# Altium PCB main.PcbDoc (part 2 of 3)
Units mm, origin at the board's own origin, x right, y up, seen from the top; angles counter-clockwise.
Board outline 326.29 x 232.51 mm, 2 copper layers (TopLayer, BottomLayer); 87 components, 134 nets, 466 pads, 108 vias.
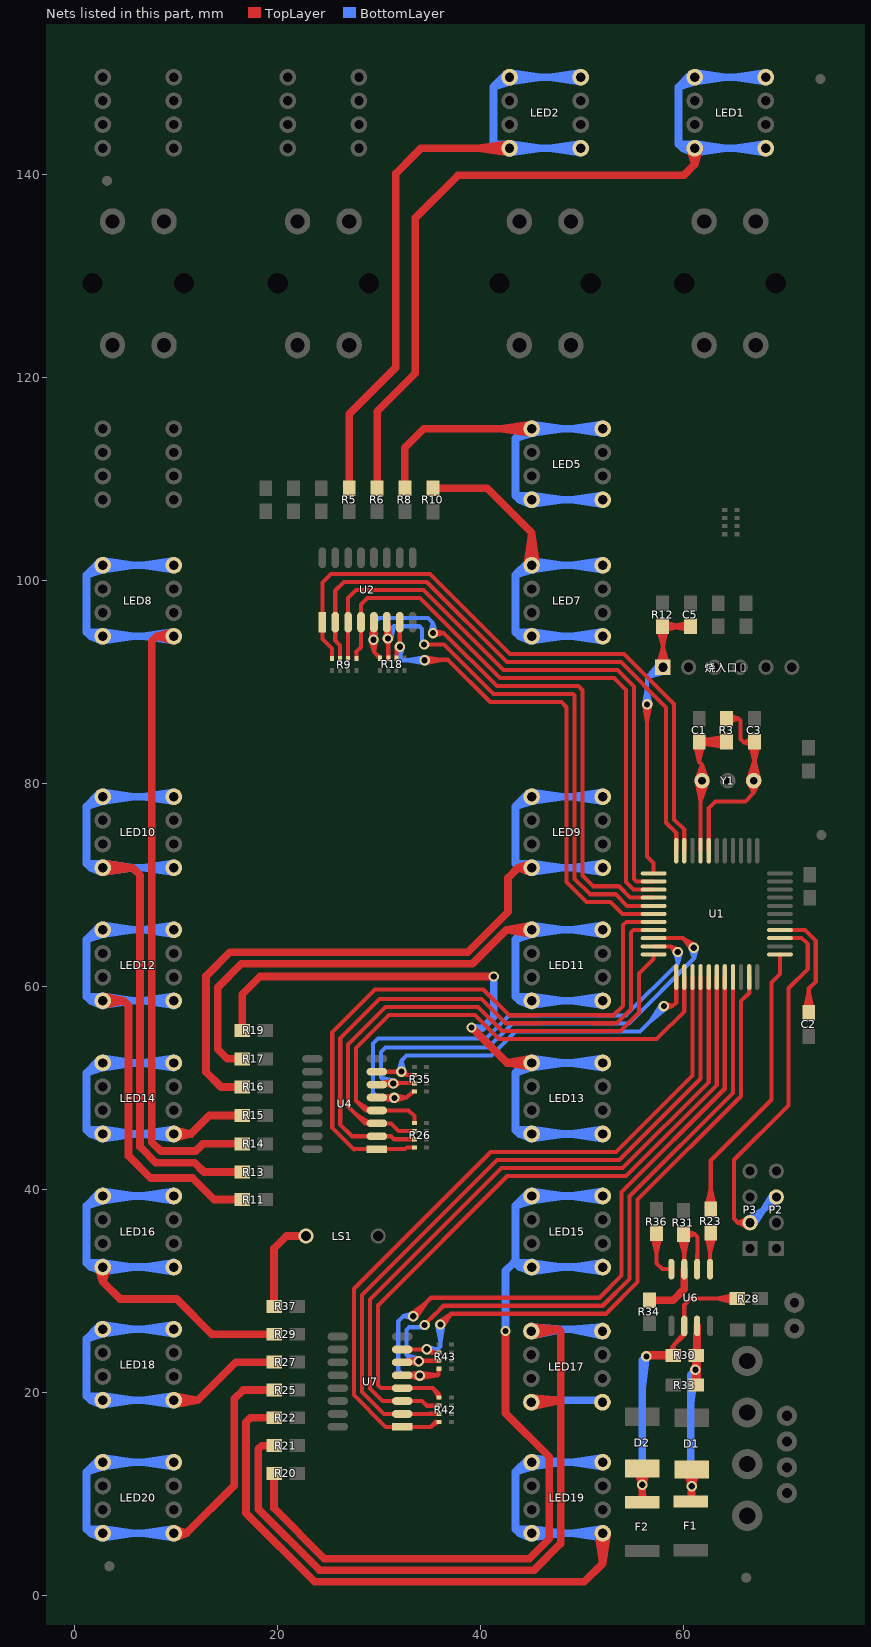
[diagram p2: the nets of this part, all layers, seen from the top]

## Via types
v1: diameter 1.016, hole 0.61, TopLayer to BottomLayer, tented both sides, 108 vias

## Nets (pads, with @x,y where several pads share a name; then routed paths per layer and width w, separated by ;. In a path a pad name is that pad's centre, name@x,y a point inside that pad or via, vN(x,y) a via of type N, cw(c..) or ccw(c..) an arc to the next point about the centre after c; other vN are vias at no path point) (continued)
LEDK4: LED2.K R5.1 | length 129
  TopLayer w0.762: R5.1@27.074,109.072 27.074,116.381 31.648,120.955 31.648,140.056 33.63,142.037 34.143,142.55 LED2.K@42.869,142.55 39.758,142.55 ; R5.1@27.074,109.199 27.074,112.12 ; LED2.K@42.837,142.107 39.758,142.55 ; LED2.K@42.837,142.993 39.758,142.55
  BottomLayer w0.762: LED2.K@42.356,149.669 41.282,148.594 ; LED2.K@42.596,149.901 41.282,148.594 ; LED2.K@42.671,149.55 LED2.K@42.869,149.55 ; LED2.K@42.703,142.138 41.282,142.949 ; LED2.K@42.901,142.107 45.981,142.55 LED2.K@42.901,142.993 ; LED2.K@42.901,149.107 45.981,149.55 LED2.K@42.901,149.993 ; LED2.K@42.918,142.992 41.282,142.949 ; LED2.K@43.051,149.144 41.282,148.594 ; LED2.K@49.671,149.55 LED2.K@42.869,149.55 ; LED2.K@49.837,142.107 46.758,142.55 ; LED2.K@49.837,142.993 46.758,142.55 ; LED2.K@49.837,149.107 46.758,149.55 ; LED2.K@49.837,149.993 46.758,149.55 ; LED2.K@49.869,149.55 46.758,149.55 ; 41.282,142.949 41.681,142.55 ; 41.282,142.949 41.282,148.594 ; 41.282,142.949 LED2.K@42.869,142.55 ; 41.282,148.594 LED2.K@42.869,149.55 ; 41.681,142.55 LED2.K@42.869,142.55 ; 41.681,142.55 42.786,142.113 41.681,142.55 ; 41.681,142.55 42.786,142.987 41.681,142.55 ; 41.681,142.55 LED2.K@42.869,142.55 ; 41.681,142.55 LED2.K@42.869,142.55 ; LED2.K@42.869,142.55 LED2.K@49.869,142.55 46.758,142.55
LEDK5: LED1.K R6.1 | length 138.8
  TopLayer w0.762: R6.1@29.824,109.072 29.824,116.642 33.579,120.396 33.579,135.687 37.795,139.903 58.674,139.903 60.046,139.903 61.099,140.957 ; R6.1@29.824,109.199 29.824,112.12 ; LED1.K@60.659,142.488 61.099,140.957 ; LED1.K@61.539,142.488 61.099,140.957 ; 61.099,140.957 LED1.K@61.099,142.55 61.099,140.957
  BottomLayer w0.762: LED1.K@60.586,149.669 59.512,148.594 ; LED1.K@60.826,149.901 59.512,148.594 ; LED1.K@60.901,149.55 LED1.K@61.099,149.55 ; LED1.K@60.933,142.138 59.512,142.949 ; LED1.K@61.131,142.107 64.211,142.55 LED1.K@61.131,142.993 ; LED1.K@61.131,149.107 64.211,149.55 LED1.K@61.131,149.993 ; LED1.K@61.148,142.992 59.512,142.949 ; LED1.K@61.281,149.144 59.512,148.594 ; LED1.K@67.901,149.55 LED1.K@61.099,149.55 ; LED1.K@68.067,142.107 64.988,142.55 ; LED1.K@68.067,142.993 64.988,142.55 ; LED1.K@68.067,149.107 64.988,149.55 ; LED1.K@68.067,149.993 64.988,149.55 ; LED1.K@68.099,149.55 64.988,149.55 ; 59.512,142.949 59.911,142.55 ; 59.512,142.949 59.512,148.594 ; 59.512,142.949 LED1.K@61.099,142.55 ; 59.512,148.594 LED1.K@61.099,149.55 ; 59.911,142.55 LED1.K@61.099,142.55 ; 59.911,142.55 61.016,142.113 59.911,142.55 ; 59.911,142.55 61.016,142.987 59.911,142.55 ; 59.911,142.55 LED1.K@61.099,142.55 ; 59.911,142.55 LED1.K@61.099,142.55 ; LED1.K@61.099,142.55 LED1.K@68.099,142.55 64.988,142.55
LEDK6: LED5.K R8.1 | length 101.1
  TopLayer w0.762: R8.1@32.549,109.072 32.549,112.051 ; R8.1@32.549,109.199 32.549,112.051 ; LED5.K@45.007,114.487 41.928,114.93 ; LED5.K@45.007,115.373 41.928,114.93 ; 32.549,112.051 32.549,113.067 34.412,114.93 LED5.K@45.039,114.93 41.928,114.93
  BottomLayer w0.762: LED5.K@44.526,115.049 43.452,113.974 ; LED5.K@44.766,115.281 43.452,113.974 ; LED5.K@44.841,114.93 LED5.K@45.039,114.93 ; LED5.K@44.873,107.518 43.452,108.329 ; LED5.K@45.071,107.487 48.151,107.93 LED5.K@45.071,108.373 ; LED5.K@45.071,114.487 48.151,114.93 LED5.K@45.071,115.373 ; LED5.K@45.088,108.372 43.452,108.329 ; LED5.K@45.221,114.524 43.452,113.974 ; LED5.K@51.841,114.93 LED5.K@45.039,114.93 ; LED5.K@52.007,107.487 48.928,107.93 ; LED5.K@52.007,108.373 48.928,107.93 ; LED5.K@52.007,114.487 48.928,114.93 ; LED5.K@52.007,115.373 48.928,114.93 ; LED5.K@52.039,114.93 48.928,114.93 ; 43.452,108.329 43.452,113.974 ; 43.452,108.329 43.851,107.93 ; 43.452,108.329 LED5.K@45.039,107.93 ; 43.452,113.974 LED5.K@45.039,114.93 ; 43.851,107.93 LED5.K@45.039,107.93 ; 43.851,107.93 44.956,107.493 43.851,107.93 ; 43.851,107.93 44.956,108.367 43.851,107.93 ; 43.851,107.93 LED5.K@45.039,107.93 ; 43.851,107.93 LED5.K@45.039,107.93 ; LED5.K@45.039,107.93 LED5.K@52.039,107.93 48.928,107.93
LEDK7: LED7.K R10.1 | length 92.6
  TopLayer w0.762: R10.1@35.307,109.055 40.652,109.055 45.039,104.668 LED7.K@45.039,101.48 ; LED7.K@44.596,101.512 45.039,104.591 LED7.K@45.483,101.512
  BottomLayer w0.762: LED7.K@44.526,101.599 43.452,100.524 ; LED7.K@44.766,101.831 43.452,100.524 ; LED7.K@44.841,101.48 LED7.K@45.039,101.48 ; LED7.K@44.873,94.068 43.452,94.879 ; LED7.K@45.071,94.037 48.151,94.48 LED7.K@45.071,94.923 ; LED7.K@45.071,101.037 48.151,101.48 LED7.K@45.071,101.923 ; LED7.K@45.088,94.922 43.452,94.879 ; LED7.K@45.221,101.074 43.452,100.524 ; LED7.K@51.841,101.48 LED7.K@45.039,101.48 ; LED7.K@52.007,94.037 48.928,94.48 ; LED7.K@52.007,94.923 48.928,94.48 ; LED7.K@52.007,101.037 48.928,101.48 ; LED7.K@52.007,101.923 48.928,101.48 ; LED7.K@52.039,101.48 48.928,101.48 ; 43.452,94.879 43.452,100.524 ; 43.452,94.879 43.851,94.48 ; 43.452,94.879 LED7.K@45.039,94.48 ; 43.452,100.524 LED7.K@45.039,101.48 ; 43.851,94.48 LED7.K@45.039,94.48 ; 43.851,94.48 44.956,94.043 43.851,94.48 ; 43.851,94.48 44.956,94.917 43.851,94.48 ; 43.851,94.48 LED7.K@45.039,94.48 ; 43.851,94.48 LED7.K@45.039,94.48 ; LED7.K@45.039,94.48 LED7.K@52.039,94.48 48.928,94.48
LEDK8: LED12.K R11.1 | length 108.9
  TopLayer w0.762: LED12.K@2.799,58.58 4.869,58.58 ; LED12.K@2.847,58.138 4.869,58.58 ; LED12.K@2.847,59.022 4.869,58.58 ; R11.1@16.417,39.008 13.791,39.008 ; R11.1@16.544,39.008 13.791,39.008 ; 4.869,58.58 5.338,58.111 5.338,43.311 7.524,41.125 11.674,41.125 13.791,39.008
  BottomLayer w0.762: LED12.K@2.286,65.699 1.212,64.624 ; LED12.K@2.526,65.931 1.212,64.624 ; LED12.K@2.601,65.58 LED12.K@2.799,65.58 ; LED12.K@2.633,58.168 1.212,58.979 ; LED12.K@2.831,58.137 5.911,58.58 LED12.K@2.831,59.023 ; LED12.K@2.831,65.137 5.911,65.58 LED12.K@2.831,66.023 ; LED12.K@2.848,59.022 1.212,58.979 ; LED12.K@2.981,65.174 1.212,64.624 ; LED12.K@9.601,65.58 LED12.K@2.799,65.58 ; LED12.K@9.767,58.137 6.688,58.58 ; LED12.K@9.767,59.023 6.688,58.58 ; LED12.K@9.767,65.137 6.688,65.58 ; LED12.K@9.767,66.023 6.688,65.58 ; LED12.K@9.799,65.58 6.688,65.58 ; 1.212,58.979 1.212,64.624 ; 1.212,58.979 1.611,58.58 ; 1.212,58.979 LED12.K@2.799,58.58 ; 1.212,64.624 LED12.K@2.799,65.58 ; 1.611,58.58 LED12.K@2.799,58.58 ; 1.611,58.58 2.716,58.143 1.611,58.58 ; 1.611,58.58 2.716,59.017 1.611,58.58 ; 1.611,58.58 LED12.K@2.799,58.58 ; 1.611,58.58 LED12.K@2.799,58.58 ; LED12.K@2.799,58.58 LED12.K@9.799,58.58 6.688,58.58
LEDK9: LED10.K R13.1 | length 122.2
  TopLayer w0.762: LED10.K@2.799,71.69 5.729,71.69 ; LED10.K@2.833,71.247 5.729,71.69 ; LED10.K@2.833,72.133 5.729,71.69 ; 13.479,41.725 R13.1@16.4,41.725 ; R13.1@16.527,41.725 12.774,41.725 11.849,42.65 8.033,42.65 6.481,44.202 6.481,70.938 5.729,71.69
  BottomLayer w0.762: LED10.K@2.286,78.809 1.212,77.734 ; LED10.K@2.526,79.041 1.212,77.734 ; LED10.K@2.601,78.69 LED10.K@2.799,78.69 ; LED10.K@2.633,71.278 1.212,72.089 ; LED10.K@2.831,71.247 5.911,71.69 LED10.K@2.831,72.133 ; LED10.K@2.831,78.247 5.911,78.69 LED10.K@2.831,79.133 ; LED10.K@2.848,72.132 1.212,72.089 ; LED10.K@2.981,78.284 1.212,77.734 ; LED10.K@9.601,78.69 LED10.K@2.799,78.69 ; LED10.K@9.767,71.247 6.688,71.69 ; LED10.K@9.767,72.133 6.688,71.69 ; LED10.K@9.767,78.247 6.688,78.69 ; LED10.K@9.767,79.133 6.688,78.69 ; LED10.K@9.799,78.69 6.688,78.69 ; 1.212,72.089 1.212,77.734 ; 1.212,72.089 1.611,71.69 ; 1.212,72.089 LED10.K@2.799,71.69 ; 1.212,77.734 LED10.K@2.799,78.69 ; 1.611,71.69 LED10.K@2.799,71.69 ; 1.611,71.69 2.716,71.253 1.611,71.69 ; 1.611,71.69 2.716,72.127 1.611,71.69 ; 1.611,71.69 LED10.K@2.799,71.69 ; 1.611,71.69 LED10.K@2.799,71.69 ; LED10.K@2.799,71.69 LED10.K@9.799,71.69 6.688,71.69
LEDK10: LED8.K R14.1 | length 140.8
  TopLayer w0.762: LED8.K@9.74,94.039 8.12,94.48 ; LED8.K@9.74,94.921 8.12,94.48 ; 13.479,44.5 R14.1@16.4,44.5 ; R14.1@16.527,44.5 12.674,44.5 11.967,43.793 8.506,43.793 7.624,44.675 7.624,93.984 8.12,94.48 ; 8.12,94.48 LED8.K@9.799,94.48 8.12,94.48
  BottomLayer w0.762: LED8.K@2.286,101.599 1.212,100.524 ; LED8.K@2.526,101.831 1.212,100.524 ; LED8.K@2.601,101.48 LED8.K@2.799,101.48 ; LED8.K@2.633,94.068 1.212,94.879 ; LED8.K@2.831,94.037 5.911,94.48 LED8.K@2.831,94.923 ; LED8.K@2.831,101.037 5.911,101.48 LED8.K@2.831,101.923 ; LED8.K@2.848,94.922 1.212,94.879 ; LED8.K@2.981,101.074 1.212,100.524 ; LED8.K@9.601,101.48 LED8.K@2.799,101.48 ; LED8.K@9.767,94.037 6.688,94.48 ; LED8.K@9.767,94.923 6.688,94.48 ; LED8.K@9.767,101.037 6.688,101.48 ; LED8.K@9.767,101.923 6.688,101.48 ; LED8.K@9.799,101.48 6.688,101.48 ; 1.212,94.879 1.212,100.524 ; 1.212,94.879 1.611,94.48 ; 1.212,94.879 LED8.K@2.799,94.48 ; 1.212,100.524 LED8.K@2.799,101.48 ; 1.611,94.48 LED8.K@2.799,94.48 ; 1.611,94.48 2.716,94.043 1.611,94.48 ; 1.611,94.48 2.716,94.917 1.611,94.48 ; 1.611,94.48 LED8.K@2.799,94.48 ; 1.611,94.48 LED8.K@2.799,94.48 ; LED8.K@2.799,94.48 LED8.K@9.799,94.48 6.688,94.48
LEDK11: LED14.K R15.1 | length 85.4
  TopLayer w0.762: LED14.K@9.799,45.47 11.485,45.47 ; LED14.K@9.858,45.029 11.485,45.47 ; LED14.K@9.858,45.911 11.485,45.47 ; 13.479,47.3 R15.1@16.4,47.3 ; R15.1@16.527,47.3 13.315,47.3 11.485,45.47
  BottomLayer w0.762: LED14.K@2.286,52.589 1.212,51.514 ; LED14.K@2.526,52.821 1.212,51.514 ; LED14.K@2.601,52.47 LED14.K@2.799,52.47 ; LED14.K@2.633,45.058 1.212,45.869 ; LED14.K@2.831,45.027 5.911,45.47 LED14.K@2.831,45.913 ; LED14.K@2.831,52.027 5.911,52.47 LED14.K@2.831,52.913 ; LED14.K@2.848,45.912 1.212,45.869 ; LED14.K@2.981,52.064 1.212,51.514 ; LED14.K@9.601,52.47 LED14.K@2.799,52.47 ; LED14.K@9.767,45.027 6.688,45.47 ; LED14.K@9.767,45.913 6.688,45.47 ; LED14.K@9.767,52.027 6.688,52.47 ; LED14.K@9.767,52.913 6.688,52.47 ; LED14.K@9.799,52.47 6.688,52.47 ; 1.212,45.869 1.212,51.514 ; 1.212,45.869 1.611,45.47 ; 1.212,45.869 LED14.K@2.799,45.47 ; 1.212,51.514 LED14.K@2.799,52.47 ; 1.611,45.47 LED14.K@2.799,45.47 ; 1.611,45.47 2.716,45.033 1.611,45.47 ; 1.611,45.47 2.716,45.907 1.611,45.47 ; 1.611,45.47 LED14.K@2.799,45.47 ; 1.611,45.47 LED14.K@2.799,45.47 ; LED14.K@2.799,45.47 LED14.K@9.799,45.47 6.688,45.47
LEDK12: LED9.K R16.1 | length 129.7
  TopLayer w0.762: R16.1@16.4,50.1 14.449,50.1 ; R16.1@16.527,50.1 14.449,50.1 ; LED9.K@44.965,71.252 43.699,71.69 ; LED9.K@44.965,72.128 43.699,71.69 ; 14.449,50.1 12.981,51.568 12.981,61.032 15.317,63.368 38.739,63.368 42.723,67.352 42.723,70.714 43.699,71.69 ; 43.699,71.69 LED9.K@45.039,71.69 43.699,71.69
  BottomLayer w0.762: LED9.K@44.526,78.809 43.452,77.734 ; LED9.K@44.766,79.041 43.452,77.734 ; LED9.K@44.841,78.69 LED9.K@45.039,78.69 ; LED9.K@44.873,71.278 43.452,72.089 ; LED9.K@45.071,71.247 48.151,71.69 LED9.K@45.071,72.133 ; LED9.K@45.071,78.247 48.151,78.69 LED9.K@45.071,79.133 ; LED9.K@45.088,72.132 43.452,72.089 ; LED9.K@45.221,78.284 43.452,77.734 ; LED9.K@51.841,78.69 LED9.K@45.039,78.69 ; LED9.K@52.007,71.247 48.928,71.69 ; LED9.K@52.007,72.133 48.928,71.69 ; LED9.K@52.007,78.247 48.928,78.69 ; LED9.K@52.007,79.133 48.928,78.69 ; LED9.K@52.039,78.69 48.928,78.69 ; 43.452,72.089 43.452,77.734 ; 43.452,72.089 43.851,71.69 ; 43.452,72.089 LED9.K@45.039,71.69 ; 43.452,77.734 LED9.K@45.039,78.69 ; 43.851,71.69 LED9.K@45.039,71.69 ; 43.851,71.69 44.956,71.253 43.851,71.69 ; 43.851,71.69 44.956,72.127 43.851,71.69 ; 43.851,71.69 LED9.K@45.039,71.69 ; 43.851,71.69 LED9.K@45.039,71.69 ; LED9.K@45.039,71.69 LED9.K@52.039,71.69 48.928,71.69
LEDK13: LED11.K R17.1 | length 122.5
  TopLayer w0.762: R17.1@16.4,52.875 15.074,52.875 ; R17.1@16.527,52.875 15.074,52.875 ; LED11.K@44.999,65.137 42.568,65.58 ; LED11.K@44.999,66.023 42.568,65.58 ; 15.074,52.875 14.124,53.825 14.124,59.9 16.449,62.225 39.213,62.225 42.568,65.58 ; 42.568,65.58 LED11.K@45.039,65.58 42.568,65.58
  BottomLayer w0.762: LED11.K@44.526,65.699 43.452,64.624 ; LED11.K@44.766,65.931 43.452,64.624 ; LED11.K@44.841,65.58 LED11.K@45.039,65.58 ; LED11.K@44.873,58.168 43.452,58.979 ; LED11.K@45.071,58.137 48.151,58.58 LED11.K@45.071,59.023 ; LED11.K@45.071,65.137 48.151,65.58 LED11.K@45.071,66.023 ; LED11.K@45.088,59.022 43.452,58.979 ; LED11.K@45.221,65.174 43.452,64.624 ; LED11.K@51.841,65.58 LED11.K@45.039,65.58 ; LED11.K@52.007,58.137 48.928,58.58 ; LED11.K@52.007,59.023 48.928,58.58 ; LED11.K@52.007,65.137 48.928,65.58 ; LED11.K@52.007,66.023 48.928,65.58 ; LED11.K@52.039,65.58 48.928,65.58 ; 43.452,58.979 43.452,64.624 ; 43.452,58.979 43.851,58.58 ; 43.452,58.979 LED11.K@45.039,58.58 ; 43.452,64.624 LED11.K@45.039,65.58 ; 43.851,58.58 LED11.K@45.039,58.58 ; 43.851,58.58 44.956,58.143 43.851,58.58 ; 43.851,58.58 44.956,59.017 43.851,58.58 ; 43.851,58.58 LED11.K@45.039,58.58 ; 43.851,58.58 LED11.K@45.039,58.58 ; LED11.K@45.039,58.58 LED11.K@52.039,58.58 48.928,58.58
LEDK14: LED13.K R19.1 | length 128.6
  TopLayer w0.762: R19.1@16.527,55.675 16.527,59.225 18.277,60.975 v1(41.3,60.975) 38.506,60.975 ; v1(39.114,55.967) 42.611,52.47 ; LED13.K@44.998,52.027 42.611,52.47 ; LED13.K@44.998,52.913 42.611,52.47 ; 42.611,52.47 LED13.K@45.039,52.47 42.611,52.47
  BottomLayer w0.762: 41.3,58.181 v1(41.3,60.975) 41.3,57.007 40.173,55.88 ; LED13.K@44.526,52.589 43.452,51.514 ; LED13.K@44.766,52.821 43.452,51.514 ; LED13.K@44.841,52.47 LED13.K@45.039,52.47 ; LED13.K@44.873,45.058 43.452,45.869 ; LED13.K@45.071,45.027 48.151,45.47 LED13.K@45.071,45.913 ; LED13.K@45.071,52.027 48.151,52.47 LED13.K@45.071,52.913 ; LED13.K@45.088,45.912 43.452,45.869 ; LED13.K@45.221,52.064 43.452,51.514 ; LED13.K@51.841,52.47 LED13.K@45.039,52.47 ; LED13.K@52.007,45.027 48.928,45.47 ; LED13.K@52.007,45.913 48.928,45.47 ; LED13.K@52.007,52.027 48.928,52.47 ; LED13.K@52.007,52.913 48.928,52.47 ; LED13.K@52.039,52.47 48.928,52.47 ; 40.173,55.88 39.201,55.88 v1(39.114,55.967) 40.173,55.88 ; 43.452,45.869 43.452,51.514 ; 43.452,45.869 43.851,45.47 ; 43.452,45.869 LED13.K@45.039,45.47 ; 43.452,51.514 LED13.K@45.039,52.47 ; 43.851,45.47 LED13.K@45.039,45.47 ; 43.851,45.47 44.956,45.033 43.851,45.47 ; 43.851,45.47 44.956,45.907 43.851,45.47 ; 43.851,45.47 LED13.K@45.039,45.47 ; 43.851,45.47 LED13.K@45.039,45.47 ; LED13.K@45.039,45.47 LED13.K@52.039,45.47 48.928,45.47
LEDK15: LED15.K R20.1 | length 140.2
  TopLayer w0.762: 19.677,9.129 R20.1@19.677,12.05 19.677,8.6 24.627,3.65 44.794,3.65 46.769,5.625 46.769,13.683 42.469,17.983 v1(42.469,26.06) 42.469,23.266
  BottomLayer w0.762: v1(42.469,26.06) 42.469,32.004 43.224,32.759 43.452,32.759 ; LED15.K@44.526,39.479 43.452,38.404 ; LED15.K@44.766,39.711 43.452,38.404 ; LED15.K@44.841,39.36 LED15.K@45.039,39.36 ; LED15.K@44.873,31.948 43.452,32.759 ; LED15.K@45.071,31.917 48.151,32.36 LED15.K@45.071,32.803 ; LED15.K@45.071,38.917 48.151,39.36 LED15.K@45.071,39.803 ; LED15.K@45.088,32.802 43.452,32.759 ; LED15.K@45.221,38.954 43.452,38.404 ; LED15.K@51.841,39.36 LED15.K@45.039,39.36 ; LED15.K@52.007,31.917 48.928,32.36 ; LED15.K@52.007,32.803 48.928,32.36 ; LED15.K@52.007,38.917 48.928,39.36 ; LED15.K@52.007,39.803 48.928,39.36 ; LED15.K@52.039,39.36 48.928,39.36 ; 43.452,32.759 43.452,38.404 ; 43.452,32.759 43.851,32.36 ; 43.452,32.759 LED15.K@45.039,32.36 ; 43.452,38.404 LED15.K@45.039,39.36 ; 43.851,32.36 LED15.K@45.039,32.36 ; 43.851,32.36 44.956,31.923 43.851,32.36 ; 43.851,32.36 44.956,32.797 43.851,32.36 ; 43.851,32.36 LED15.K@45.039,32.36 ; 43.851,32.36 LED15.K@45.039,32.36 ; LED15.K@45.039,32.36 LED15.K@52.039,32.36 48.928,32.36
LEDK16: LED17.K R21.1 | length 118.5
  TopLayer w0.762: R21.1@19.55,14.775 18.449,14.775 ; R21.1@19.677,14.775 18.449,14.775 ; LED17.K@45.014,19.055 47.912,19.25 ; LED17.K@45.014,26.055 47.715,26.25 ; LED17.K@45.018,19.5 47.912,19.25 ; LED17.K@45.019,26.5 47.715,26.25 ; LED17.K@45.039,19.25 47.912,19.25 ; LED17.K@45.039,26.25 47.715,26.25 ; LED17.K@45.078,18.615 47.912,19.25 ; LED17.K@45.082,25.616 47.715,26.25 ; 18.449,14.775 18.124,14.45 18.124,8.536 24.154,2.507 45.268,2.507 47.912,5.152 47.912,26.053 47.715,26.25
  BottomLayer w0.762: LED17.K@44.841,26.25 45.039,26.25 LED17.K@51.841,26.25 ; LED17.K@45.014,26.055 48.144,26.25 ; LED17.K@45.018,26.5 48.144,26.25 ; LED17.K@45.039,19.25 LED17.K@52.039,19.25 ; LED17.K@45.073,25.615 48.144,26.25 ; LED17.K@51.955,25.615 48.88,26.25 ; LED17.K@52.01,26.5 48.88,26.25 ; LED17.K@52.014,26.055 48.88,26.25
LEDK17: LED19.K R22.1 | length 133.3
  TopLayer w0.762: R22.1@19.55,17.525 17.349,17.525 ; R22.1@19.677,17.525 17.349,17.525 ; LED19.K@51.596,6.107 52.039,3.17 ; LED19.K@52.039,6.14 52.039,3.17 ; LED19.K@52.482,6.107 52.039,3.17 ; 17.349,17.525 16.899,17.075 16.899,8.145 23.68,1.364 50.234,1.364 52.039,3.17
  BottomLayer w0.762: LED19.K@44.526,13.259 43.452,12.184 ; LED19.K@44.766,13.491 43.452,12.184 ; LED19.K@44.841,13.14 LED19.K@45.039,13.14 ; LED19.K@44.873,5.728 43.452,6.539 ; LED19.K@45.071,5.697 48.151,6.14 LED19.K@45.071,6.583 ; LED19.K@45.071,12.697 48.151,13.14 LED19.K@45.071,13.583 ; LED19.K@45.088,6.582 43.452,6.539 ; LED19.K@45.221,12.734 43.452,12.184 ; LED19.K@51.841,13.14 LED19.K@45.039,13.14 ; LED19.K@52.007,5.697 48.928,6.14 ; LED19.K@52.007,6.583 48.928,6.14 ; LED19.K@52.007,12.697 48.928,13.14 ; LED19.K@52.007,13.583 48.928,13.14 ; LED19.K@52.039,13.14 48.928,13.14 ; 43.452,6.539 43.452,12.184 ; 43.452,6.539 43.851,6.14 ; 43.452,6.539 LED19.K@45.039,6.14 ; 43.452,12.184 LED19.K@45.039,13.14 ; 43.851,6.14 LED19.K@45.039,6.14 ; 43.851,6.14 44.956,5.703 43.851,6.14 ; 43.851,6.14 44.956,6.577 43.851,6.14 ; 43.851,6.14 LED19.K@45.039,6.14 ; 43.851,6.14 LED19.K@45.039,6.14 ; LED19.K@45.039,6.14 LED19.K@52.039,6.14 48.928,6.14
LEDK18: LED20.K R25.1 | length 97.8
  TopLayer w0.762: LED20.K@9.799,6.14 11.04,6.14 ; LED20.K@9.879,5.703 11.04,6.14 ; LED20.K@9.879,6.577 11.04,6.14 ; 16.629,20.25 R25.1@19.55,20.25 ; R25.1@19.677,20.25 16.624,20.25 15.756,19.382 15.756,10.856 11.04,6.14
  BottomLayer w0.762: LED20.K@2.286,13.259 1.212,12.184 ; LED20.K@2.526,13.491 1.212,12.184 ; LED20.K@2.601,13.14 LED20.K@2.799,13.14 ; LED20.K@2.633,5.728 1.212,6.539 ; LED20.K@2.831,5.697 5.911,6.14 LED20.K@2.831,6.583 ; LED20.K@2.831,12.697 5.911,13.14 LED20.K@2.831,13.583 ; LED20.K@2.848,6.582 1.212,6.539 ; LED20.K@2.981,12.734 1.212,12.184 ; LED20.K@9.601,13.14 LED20.K@2.799,13.14 ; LED20.K@9.767,5.697 6.688,6.14 ; LED20.K@9.767,6.583 6.688,6.14 ; LED20.K@9.767,12.697 6.688,13.14 ; LED20.K@9.767,13.583 6.688,13.14 ; LED20.K@9.799,13.14 6.688,13.14 ; 1.212,6.539 1.611,6.14 ; 1.212,6.539 1.212,12.184 ; 1.212,6.539 LED20.K@2.799,6.14 ; 1.212,12.184 LED20.K@2.799,13.14 ; 1.611,6.14 LED20.K@2.799,6.14 ; 1.611,6.14 2.716,5.703 1.611,6.14 ; 1.611,6.14 2.716,6.577 1.611,6.14 ; 1.611,6.14 LED20.K@2.799,6.14 ; 1.611,6.14 LED20.K@2.799,6.14 ; LED20.K@2.799,6.14 LED20.K@9.799,6.14 6.688,6.14
LEDK19: LED18.K R27.1 | length 90.7
  TopLayer w0.762: LED18.K@9.799,19.25 12.149,19.25 ; LED18.K@9.841,18.807 12.149,19.25 ; LED18.K@9.841,19.692 12.149,19.25 ; 16.629,23 R27.1@19.55,23 ; R27.1@19.677,23 15.899,23 12.149,19.25
  BottomLayer w0.762: LED18.K@2.286,26.369 1.212,25.294 ; LED18.K@2.526,26.601 1.212,25.294 ; LED18.K@2.601,26.25 LED18.K@2.799,26.25 ; LED18.K@2.633,18.838 1.212,19.649 ; LED18.K@2.831,18.807 5.911,19.25 LED18.K@2.831,19.693 ; LED18.K@2.831,25.807 5.911,26.25 LED18.K@2.831,26.693 ; LED18.K@2.848,19.692 1.212,19.649 ; LED18.K@2.981,25.844 1.212,25.294 ; LED18.K@9.601,26.25 LED18.K@2.799,26.25 ; LED18.K@9.767,18.807 6.688,19.25 ; LED18.K@9.767,19.693 6.688,19.25 ; LED18.K@9.767,25.807 6.688,26.25 ; LED18.K@9.767,26.693 6.688,26.25 ; LED18.K@9.799,26.25 6.688,26.25 ; 1.212,19.649 1.212,25.294 ; 1.212,19.649 1.611,19.25 ; 1.212,19.649 LED18.K@2.799,19.25 ; 1.212,25.294 LED18.K@2.799,26.25 ; 1.611,19.25 LED18.K@2.799,19.25 ; 1.611,19.25 2.716,18.813 1.611,19.25 ; 1.611,19.25 2.716,19.687 1.611,19.25 ; 1.611,19.25 LED18.K@2.799,19.25 ; 1.611,19.25 LED18.K@2.799,19.25 ; LED18.K@2.799,19.25 LED18.K@9.799,19.25 6.688,19.25
LEDK20: LED16.K R29.1 | length 99.3
  TopLayer w0.762: LED16.K@2.36,32.291 2.799,30.932 ; LED16.K@3.238,32.291 2.799,30.932 ; 16.629,25.75 R29.1@19.55,25.75 ; R29.1@19.677,25.75 13.549,25.75 10.074,29.225 4.506,29.225 2.799,30.932 ; 2.799,30.932 LED16.K@2.799,32.36 2.799,30.932
  BottomLayer w0.762: LED16.K@2.286,39.479 1.212,38.404 ; LED16.K@2.526,39.711 1.212,38.404 ; LED16.K@2.601,39.36 LED16.K@2.799,39.36 ; LED16.K@2.633,31.948 1.212,32.759 ; LED16.K@2.831,31.917 5.911,32.36 LED16.K@2.831,32.803 ; LED16.K@2.831,38.917 5.911,39.36 LED16.K@2.831,39.803 ; LED16.K@2.848,32.802 1.212,32.759 ; LED16.K@2.981,38.954 1.212,38.404 ; LED16.K@9.601,39.36 LED16.K@2.799,39.36 ; LED16.K@9.767,31.917 6.688,32.36 ; LED16.K@9.767,32.803 6.688,32.36 ; LED16.K@9.767,38.917 6.688,39.36 ; LED16.K@9.767,39.803 6.688,39.36 ; LED16.K@9.799,39.36 6.688,39.36 ; 1.212,32.759 1.212,38.404 ; 1.212,32.759 1.611,32.36 ; 1.212,32.759 LED16.K@2.799,32.36 ; 1.212,38.404 LED16.K@2.799,39.36 ; 1.611,32.36 LED16.K@2.799,32.36 ; 1.611,32.36 2.716,31.923 1.611,32.36 ; 1.611,32.36 2.716,32.797 1.611,32.36 ; 1.611,32.36 LED16.K@2.799,32.36 ; 1.611,32.36 LED16.K@2.799,32.36 ; LED16.K@2.799,32.36 LED16.K@9.799,32.36 6.688,32.36
LOUT1: R9.8 U1.10 U2.1 | length 67.6
  TopLayer w0.406: U2.1@24.429,95.24 24.429,94.22 ; U2.1@24.429,96.51 24.429,98.11 ; R9.8@25.374,92.3 25.374,93.275 ; R9.8@25.374,92.35 25.374,93.275 ; U1.10@60.074,73.373 60.074,75.45 ; U1.10@60.074,74.44 60.074,75.45 ; 24.429,94.22 25.374,93.275 ; 24.429,94.22 U2.1@24.429,95.875 24.429,99.769 25.273,100.612 35.037,100.612 42.924,92.725 54.149,92.725 59.074,87.8 59.074,76.45 60.074,75.45
LOUT2: R9.7 U1.11 U2.2 | length 64.1
  TopLayer w0.406: U2.2@25.699,95.24 25.699,94.064 ; U2.2@25.699,96.51 25.699,98.11 ; R9.7@26.174,92.3 26.174,93.589 ; R9.7@26.174,92.35 26.174,93.589 ; U1.11@59.286,73.373 59.286,75.124 ; U1.11@59.286,74.44 59.286,75.124 ; 25.699,94.064 U2.2@25.699,95.875 25.699,98.975 26.549,99.825 34.708,99.825 42.596,91.938 53.823,91.938 58.287,87.474 58.287,76.124 59.286,75.124 ; 25.699,94.064 26.174,93.589
LOUT3: R9.6 U1.13 U2.3 | length 63.1
  TopLayer w0.406: 26.969,93.64 U2.3@26.969,95.24 ; U2.3@26.969,96.51 26.969,98.11 ; R9.6@26.974,92.3 26.969,92.305 U2.3@26.969,95.875 26.969,98.245 27.761,99.037 34.382,99.037 42.269,91.15 53.497,91.15 55.124,89.523 55.124,70.6 55.374,70.35 ; U1.13@55.984,70.35 55.374,70.35 ; U1.13@57.051,70.35 55.374,70.35
LOUT4: R9.5 U1.14 U2.4 | length 61.7
  TopLayer w0.406: R9.5@27.774,92.3 27.774,92.907 ; R9.5@27.774,92.35 27.774,92.907 ; 28.239,93.64 U2.4@28.239,95.24 ; U2.4@28.239,96.51 28.239,97.603 ; U1.14@55.984,69.538 55.073,69.538 ; U1.14@57.051,69.538 55.073,69.538 ; 27.774,92.907 27.757,92.925 28.239,93.408 U2.4@28.239,95.875 28.239,97.603 ; 28.239,97.603 28.886,98.25 34.056,98.25 41.943,90.363 53.171,90.363 54.337,89.197 54.337,70.274 55.073,69.538
LOUT5: R18.8 U1.15 U2.5 | length 79.4
  TopLayer w0.406: v1@29.171,94.183 U2.5@29.509,95.875 ; v1@29.173,94.103 29.509,92.94 ; v1@29.174,94.202 U2.5@29.509,95.24 ; v1@29.777,94.183 U2.5@29.509,95.24 ; v1@29.778,94.12 29.509,92.94 ; v1@29.778,94.171 U2.5@29.509,95.875 ; R18.8@30.124,92.325 29.509,92.94 ; R18.8@30.124,92.375 29.509,92.94 ; v1@35.362,95.102 36.371,94.822 ; v1@35.375,94.499 36.371,94.822 ; U1.15@55.984,68.75 54.747,68.75 ; U1.15@57.051,68.75 54.747,68.75 ; v1(29.474,94.15) v1@29.509,94.15 ; v1(29.474,94.15) U2.5@29.509,95.24 ; v1(29.474,94.15) 29.509,92.94 ; v1(29.474,94.15) U2.5@29.509,95.875 ; 29.509,92.94 v1@29.509,94.15 ; v1@29.509,94.15 U2.5@29.509,95.875 ; v1@29.509,94.15 U2.5@29.509,95.24 ; 36.371,94.822 35.346,94.822 v1(35.324,94.8) 36.371,94.822 ; 36.371,94.822 41.617,89.575 49.649,89.575 50.049,89.175 50.049,70.925 51.099,69.875 53.622,69.875 54.747,68.75
  BottomLayer w0.406: v1@29.171,94.179 29.474,95.725 ; v1(29.474,94.15) 29.474,95.725 ; v1@29.778,94.179 29.474,95.725 ; v1@35.023,94.848 35.324,95.775 ; v1(35.324,94.8) 35.324,95.775 ; v1@35.625,94.848 35.324,95.775 ; 29.474,95.725 30.024,96.275 34.824,96.275 35.324,95.775
LOUT6: R18.7 U1.16 U2.6 | length 74.9
  TopLayer w0.406: v1@30.58,94.275 U2.6@30.779,95.24 ; v1@30.582,94.3 U2.6@30.924,95.73 ; v1@30.594,94.167 30.924,93.634 ; U2.6@30.779,95.875 U2.6@30.924,95.73 ; R18.7@30.924,92.325 U2.6@30.924,95.73 ; R18.7@30.924,92.375 v1@30.924,93.794 ; v1@31.179,94.339 U2.6@30.779,95.24 ; v1@31.184,94.205 30.924,93.634 ; v1@31.188,94.283 U2.6@30.924,95.73 ; v1(34.449,93.675) 34.464,93.69 36.389,93.69 41.291,88.788 49.124,88.788 49.262,88.65 49.262,70.599 50.773,69.088 53.296,69.088 54.446,67.937 U1.16@57.051,67.937 ; 54.562,67.937 U1.16@55.984,67.937 ; U2.6@30.779,95.24 30.924,93.634 ; U2.6@30.779,95.24 v1(30.884,94.26) ; v1(30.884,94.26) U2.6@30.924,95.73 ; v1(30.884,94.26) 30.924,93.634
  BottomLayer w0.406: v1@30.629,94.427 31.499,95.475 ; v1@30.899,94.275 30.899,94.875 ; v1@31.17,94.154 31.499,95.475 ; v1(34.449,93.675) 34.232,93.892 34.232,95.217 33.974,95.475 31.499,95.475 ; v1(30.884,94.26) 31.499,95.475 ; v1(30.884,94.26) 30.899,94.875 ; v1(30.884,94.26) 30.899,94.875 ; 30.899,94.875 31.499,95.475 ; 30.899,94.875 30.591,94.343 30.899,94.875 ; 30.899,94.875 31.181,94.328 30.899,94.875
LOUT7: R18.6 U1.17 U2.7 | length 73.2
  TopLayer w0.406: R18.6@31.724,92.325 31.724,92.95 ; R18.6@31.724,92.375 31.724,92.95 ; v1@32.049,93.64 U2.7@32.049,95.24 ; U2.7@32.049,95.875 32.049,93.275 31.724,92.95 ; v1@32.064,93.29 v1(32.064,93.464) ; v1@34.518,92.429 36.228,92.171 ; v1@34.534,91.822 36.228,92.171 ; 54.562,67.15 U1.17@55.984,67.15 ; U1.17@57.051,67.15 53.974,67.15 52.824,68.3 50.447,68.3 48.474,70.273 48.474,87.5 47.974,88.001 40.965,88.001 36.795,92.171 34.545,92.171 v1(34.499,92.125) 36.228,92.171 ; 31.724,92.95 v1@32.269,93.238 ; 31.724,92.95 v1@31.776,93.564 ; 31.724,92.95 v1(32.064,93.464) ; 31.724,92.95 v1@32.269,93.238 ; 31.724,92.95 v1@31.776,93.564 ; 31.724,92.95 v1(32.064,93.464) ; 31.724,92.95 v1@32.269,93.238 ; 31.724,92.95 v1@31.776,93.564 ; 31.724,92.95 v1(32.064,93.464)
  BottomLayer w0.406: v1@31.762,93.42 32.064,92.41 ; v1@32.365,93.42 32.064,92.41 ; v1@34.472,91.821 32.772,92.125 ; v1@34.472,92.429 32.772,92.125 ; 32.064,92.41 v1(32.064,93.464) 32.064,92.41 ; 32.064,92.41 32.349,92.125 v1(34.499,92.125) 32.772,92.125
LOUT8: R26.8 U1.18 U4.1 | length 66.7
  TopLayer w0.406: U4.1@29.164,43.98 27.589,43.98 ; U4.1@30.434,43.98 32.034,43.98 ; R26.8@33.442,44.142 32.749,44.15 ; R26.8@33.492,44.142 33.483,44.15 32.749,44.15 ; 54.562,66.363 U1.18@55.984,66.363 ; U1.18@57.051,66.363 54.374,66.363 54.051,66.04 54.051,58.096 53.125,57.17 51.455,57.17 51.45,57.175 45.628,57.175 45.623,57.17 42.796,57.17 40.276,59.69 29.616,59.69 25.398,55.472 25.398,46.095 27.551,43.942 27.589,43.98 ; 27.589,43.98 U4.1@29.799,43.98 32.579,43.98 32.749,44.15
LOUT9: R26.7 U1.19 U4.2 | length 62.7
  TopLayer w0.406: 27.564,45.25 U4.2@29.164,45.25 ; U4.2@30.434,45.25 31.199,45.25 ; 32.022,44.95 R26.7@33.442,44.942 ; R26.7@33.492,44.942 33.483,44.95 31.499,44.95 31.199,45.25 ; U1.19@55.984,65.55 55.085,65.55 ; U1.19@57.051,65.55 55.085,65.55 ; 31.199,45.25 U4.2@29.799,45.25 27.356,45.25 26.185,46.421 26.185,54.864 30.074,58.752 40.101,58.752 42.47,56.383 45.949,56.383 45.954,56.388 51.124,56.388 51.129,56.383 53.452,56.383 54.839,57.77 54.839,65.303 55.085,65.55
LOUT10: R26.6 U1.22 U4.3 | length 57.4
  TopLayer w0.406: 27.652,47.479 U4.3@29.164,46.52 ; U4.3@30.434,46.52 31.179,46.52 ; 32.022,45.75 R26.6@33.442,45.742 ; R26.6@33.492,45.742 33.483,45.75 31.949,45.75 31.179,46.52 ; 28.611,46.52 U4.3@29.799,46.52 31.179,46.52 ; 28.611,46.52 26.973,48.158 26.973,54.269 30.669,57.965 39.774,57.965 42.144,55.595 53.778,55.595 55.626,57.444 55.626,61.265 57.051,62.69 ; 28.611,46.52 U4.3@29.164,46.52 ; 28.611,46.52 U4.3@29.164,46.52 ; 57.051,62.69 U1.22@57.051,63.162 57.051,62.69
LOUT11: R26.5 U1.24 U4.4 | length 57.1
  TopLayer w0.406: U4.4@30.434,47.79 32.034,47.79 ; R26.5@33.492,46.542 33.492,47.23 32.931,47.79 U4.4@29.799,47.79 28.687,47.79 ; 60.074,58.438 U1.24@60.074,59.86 ; U1.24@60.074,60.927 60.074,57.534 57.348,54.808 41.818,54.808 39.448,57.177 30.995,57.177 27.76,53.943 27.76,48.717 ; 27.76,48.717 28.687,47.79 ; 27.76,48.717 U4.4@29.164,47.79 ; 28.687,47.79 U4.4@29.164,47.79 ; 28.687,47.79 U4.4@29.164,47.79
LOUT12: R35.8 U1.21 U4.5 | length 73.5
  TopLayer w0.406: v1@31.472,48.725 U4.5@30.434,49.06 ; v1@31.491,48.722 U4.5@29.799,49.06 ; v1@31.491,49.328 U4.5@30.434,49.06 ; v1@31.503,49.329 U4.5@29.799,49.06 ; v1@31.554,49.328 32.734,49.06 ; v1@31.571,48.724 32.734,49.06 ; R35.8@33.349,49.675 32.734,49.06 ; R35.8@33.442,49.667 32.734,49.06 ; U1.21@57.051,63.95 58.725,63.95 ; U1.21@58.118,63.95 58.725,63.95 ; v1@59.211,63.193 58.725,63.95 ; v1@59.579,63.667 58.725,63.95 ; U4.5@29.799,49.06 v1@31.524,49.06 ; U4.5@29.799,49.06 v1(31.524,49.025) ; U4.5@30.434,49.06 v1@31.524,49.06 ; U4.5@30.434,49.06 v1(31.524,49.025) ; v1(31.524,49.025) v1@31.524,49.06 ; v1(31.524,49.025) 32.734,49.06 ; v1@31.524,49.06 32.734,49.06 ; 58.725,63.95 59.276,63.398 v1(59.436,63.398) 58.725,63.95
  BottomLayer w0.406: v1@31.495,48.722 29.949,49.025 ; v1@31.495,49.328 29.949,49.025 ; v1@59.134,63.357 59.436,62.281 ; v1@59.738,63.357 59.436,62.281 ; 29.949,49.025 29.399,49.575 29.399,54.375 29.899,54.875 40.533,54.875 42.808,57.15 54.305,57.15 59.436,62.281 ; 29.949,49.025 v1(31.524,49.025) 29.949,49.025 ; 59.436,62.281 v1(59.436,63.398) 59.436,62.281
LOUT13: R35.7 U1.20 U4.6 | length 78.4
  TopLayer w0.406: U4.6@29.799,50.33 U4.6@29.944,50.475 ; v1@31.335,50.729 U4.6@30.434,50.33 ; v1@31.374,50.133 U4.6@29.944,50.475 ; v1@31.391,50.739 U4.6@29.944,50.475 ; v1@31.399,50.131 U4.6@30.434,50.33 ; v1@31.469,50.735 32.041,50.475 ; v1@31.471,50.735 32.022,50.475 ; v1@31.507,50.145 32.041,50.475 ; v1@31.51,50.146 32.022,50.475 ; R35.7@33.349,50.475 U4.6@29.944,50.475 ; R35.7@33.442,50.467 32.022,50.475 ; U1.20@57.051,64.762 59.952,64.762 ; U1.20@58.118,64.762 59.54,64.762 ; v1@60.783,63.602 59.952,64.762 ; v1@61.19,64.051 59.952,64.762 ; U4.6@29.944,50.475 v1(31.414,50.435) ; U4.6@30.434,50.33 32.041,50.475 ; U4.6@30.434,50.33 v1(31.414,50.435) ; v1(31.414,50.435) 32.022,50.475 ; v1(31.414,50.435) 32.041,50.475 ; 59.952,64.762 60.96,63.754 v1(61.011,63.805) 59.952,64.762
  BottomLayer w0.406: v1@31.247,50.18 30.199,51.05 ; v1@31.399,50.45 30.799,50.45 ; v1@31.52,50.721 30.199,51.05 ; v1@60.709,63.762 61.009,62.74 ; v1@61.312,63.761 61.009,62.74 ; 30.199,51.05 30.199,53.525 30.649,53.975 40.747,53.975 43.134,56.363 54.631,56.363 61.009,62.74 ; 30.199,51.05 30.799,50.45 ; 30.199,51.05 v1(31.414,50.435) ; 30.799,50.45 31.331,50.142 30.799,50.45 ; 30.799,50.45 31.346,50.732 30.799,50.45 ; 30.799,50.45 v1(31.414,50.435) ; 30.799,50.45 v1(31.414,50.435) ; 61.009,62.74 v1(61.011,63.805) v1(61.011,63.805) 61.009,62.74
LOUT14: R35.6 U1.23 U4.7 | length 56.1
  TopLayer w0.406: U4.7@29.799,51.6 32.399,51.6 32.724,51.275 ; U4.7@30.434,51.6 v1@32.034,51.6 ; v1@32.385,51.615 v1(32.21,51.615) ; R35.6@33.349,51.275 32.724,51.275 ; R35.6@33.442,51.267 32.724,51.275 ; v1(58.064,58.064) 58.928,58.064 ; v1@58.118,57.764 58.928,58.064 ; v1@58.118,58.364 58.928,58.064 ; 59.286,58.438 U1.23@59.286,59.86 ; U1.23@59.286,60.927 59.286,58.423 58.928,58.064 ; v1@32.11,51.327 32.724,51.275 ; v1@32.11,51.327 32.724,51.275 ; v1@32.11,51.327 32.724,51.275 ; v1(32.21,51.615) 32.724,51.275 ; v1(32.21,51.615) 32.724,51.275 ; v1(32.21,51.615) 32.724,51.275 ; v1@32.436,51.819 32.724,51.275 ; v1@32.436,51.819 32.724,51.275 ; v1@32.436,51.819 32.724,51.275
  BottomLayer w0.406: v1@31.909,51.658 32.21,52.683 ; v1(32.21,51.615) 32.21,52.683 ; v1@32.512,51.658 32.21,52.683 ; v1@57.822,58.249 56.783,56.631 ; v1(58.064,58.064) 56.783,56.631 ; v1@58.275,57.844 56.783,56.631 ; v1@58.318,58.166 55.728,55.575 43.46,55.575 41.073,53.188 32.715,53.188 32.21,52.683
LOUT15: R42.8 U1.25 U7.1 | length 77
  TopLayer w0.406: U7.1@31.664,16.63 30.667,16.63 ; U7.1@32.934,16.63 34.534,16.63 ; 60.887,58.438 U1.25@60.887,59.86 ; U1.25@60.887,60.927 60.887,51.235 53.34,43.688 41.011,43.688 27.549,30.226 27.549,19.748 30.667,16.63 ; 30.667,16.63 U7.1@32.299,16.63 35.104,16.63 ; 35.104,16.63 35.599,17.125 35.885,17.12 35.104,16.63
LOUT16: R42.7 U1.26 U7.2 | length 75.2
  TopLayer w0.406: U7.2@31.664,17.9 30.511,17.9 ; U7.2@32.934,17.9 34.534,17.9 ; 61.674,58.438 U1.26@61.674,59.86 ; U1.26@61.674,60.927 61.674,50.908 53.666,42.901 41.621,42.901 28.337,29.616 28.337,20.074 30.511,17.9 ; 30.511,17.9 U7.2@32.299,17.9 34.999,17.9 35.021,17.922 ; 35.021,17.922 35.599,17.922 35.885,17.92 35.021,17.922
LOUT17: R42.6 U1.27 U7.3 | length 74.6
  TopLayer w0.406: U7.3@31.664,19.17 30.354,19.17 ; U7.3@32.934,19.17 34.254,19.17 ; 62.487,58.438 U1.27@62.487,59.86 ; U1.27@62.487,60.927 62.487,50.608 53.992,42.113 42.078,42.113 29.124,29.159 29.124,20.4 30.354,19.17 ; 30.354,19.17 U7.3@32.299,19.17 34.254,19.17 ; 34.254,19.17 34.715,18.709 ; 34.715,18.709 35.583,18.709 ; 34.715,18.709 R42.6@35.885,18.72 ; 35.583,18.709 35.599,18.725 R42.6@35.885,18.72 ; 35.583,18.709 R42.6@35.885,18.72 ; 35.583,18.709 R42.6@35.885,18.72
LOUT18: R42.5 U1.28 U7.4 | length 73.5
  TopLayer w0.406: U7.4@31.664,20.44 30.198,20.44 ; U7.4@32.934,20.44 34.534,20.44 ; R42.5@35.885,19.52 35.338,20.44 ; 63.274,58.438 U1.28@63.274,59.86 ; U1.28@63.274,60.927 63.274,50.282 54.318,41.326 42.637,41.326 29.912,28.6 29.912,20.726 30.198,20.44 ; 30.198,20.44 U7.4@32.299,20.44 35.338,20.44 ; 35.338,20.44 35.935,19.844 ; 35.935,19.844 R42.5@35.935,19.52 35.935,19.844
LOUT19: R43.8 U1.29 U7.5 | length 98.4
  TopLayer w0.406: v1@33.173,27.754 34.717,28.911 ; v1@33.609,27.331 34.717,28.911 ; v1@33.972,21.375 U7.5@32.934,21.71 ; v1@33.991,21.372 U7.5@32.299,21.71 ; v1@33.991,21.978 U7.5@32.934,21.71 ; v1@34.003,21.979 U7.5@32.299,21.71 ; v1@34.045,21.979 35.752,21.71 ; v1@34.057,21.372 35.752,21.71 ; R43.8@35.849,22.325 35.849,21.778 35.782,21.71 v1@34.024,21.71 ; 64.062,58.438 U1.29@64.062,59.86 ; U1.29@64.062,60.927 64.062,49.926 53.904,39.769 53.904,31.53 51.714,29.34 35.146,29.34 33.353,27.547 v1(33.374,27.525) 34.717,28.911 ; U7.5@32.299,21.71 v1@34.024,21.71 ; U7.5@32.299,21.71 v1(34.024,21.675) ; U7.5@32.934,21.71 v1@34.024,21.71 ; U7.5@32.934,21.71 v1(34.024,21.675) ; v1(34.024,21.675) v1@34.024,21.71 ; v1(34.024,21.675) 35.752,21.71
  BottomLayer w0.406: v1@33.327,27.224 32.399,27.525 ; v1@33.327,27.826 32.399,27.525 ; v1@33.995,21.372 32.449,21.675 ; v1@33.995,21.978 32.449,21.675 ; 32.399,27.525 v1(33.374,27.525) 32.399,27.525 ; 32.399,27.525 31.899,27.025 31.899,22.225 32.449,21.675 ; 32.449,21.675 v1(34.024,21.675) 32.449,21.675
LOUT20: R43.7 U1.30 U7.6 | length 83.3
  TopLayer w0.406: U7.6@32.299,22.98 U7.6@32.444,23.125 ; v1@33.835,23.379 U7.6@32.934,22.98 ; v1@33.874,22.783 U7.6@32.444,23.125 ; v1@33.891,23.389 U7.6@32.444,23.125 ; v1@33.899,22.781 U7.6@32.934,22.98 ; v1@34.484,26.665 v1(34.499,26.65) 34.499,26.695 35.597,27.792 35.615,27.792 36.376,28.553 52.041,28.553 54.691,31.203 54.691,39.337 64.874,49.52 U1.30@64.874,60.927 ; R43.7@35.935,23.152 35.92,23.138 33.967,23.138 v1@33.954,23.125 ; 64.874,58.438 U1.30@64.874,59.86 ; U7.6@32.444,23.125 v1@33.954,23.125 ; U7.6@32.444,23.125 v1(33.914,23.085) U7.6@32.934,22.98 ; U7.6@32.934,22.98 v1@33.954,23.125
  BottomLayer w0.406: v1@33.747,22.83 32.699,23.7 ; v1@33.899,23.1 33.299,23.1 ; v1@34.02,23.371 32.699,23.7 ; v1(34.499,26.65) 34.282,26.433 32.957,26.433 32.699,26.175 32.699,23.7 ; 32.699,23.7 33.299,23.1 ; 32.699,23.7 v1(33.914,23.085) ; 33.299,23.1 33.831,22.792 33.299,23.1 ; 33.299,23.1 33.846,23.382 33.299,23.1 ; 33.299,23.1 v1(33.914,23.085) ; 33.299,23.1 v1(33.914,23.085)
LOUT21: R43.6 U1.32 U7.7 | length 85.7
  TopLayer w0.406: U7.7@32.299,24.25 34.899,24.25 35.224,23.925 ; U7.7@32.934,24.25 v1@34.534,24.25 ; v1@34.885,24.265 v1(34.71,24.265) ; v1@35.857,26.936 37.114,27.765 ; R43.6@35.885,23.952 35.251,23.952 ; R43.6@35.935,23.952 35.251,23.952 ; v1@36.004,26.746 v1(36.049,26.7) 37.114,27.765 ; v1@36.285,26.507 37.114,27.765 ; U1.32@66.475,59.86 66.475,59.363 ; U1.32@66.475,60.927 66.475,59.363 ; v1@34.627,23.972 35.251,23.952 ; v1@34.627,23.972 35.251,23.952 ; v1@34.627,23.972 35.251,23.952 ; v1(34.71,24.265) 35.251,23.952 ; v1(34.71,24.265) 35.251,23.952 ; v1(34.71,24.265) 35.224,23.925 ; v1(34.71,24.265) 35.251,23.952 ; v1(34.71,24.265) 35.224,23.925 ; v1@34.922,24.483 35.251,23.952 ; v1@34.922,24.483 35.251,23.952 ; v1@34.922,24.483 35.251,23.952 ; 35.224,23.925 35.251,23.952 ; 35.224,23.925 34.936,24.469 35.224,23.925 ; 35.224,23.925 34.61,23.977 35.224,23.925 ; 37.114,27.765 52.367,27.765 55.479,30.877 55.479,39.007 65.662,49.19 65.662,58.55 66.475,59.363
  BottomLayer w0.406: v1(34.71,24.265) 35.764,24.265 ; v1@34.754,23.963 35.764,24.265 ; v1@34.754,24.566 35.764,24.265 ; v1@35.746,26.673 36.049,24.973 ; v1@36.353,26.673 36.049,24.973 ; 35.764,24.265 36.049,24.55 v1(36.049,26.7) 36.049,24.973
MCU_1: 
MCU_2: 
NetC2_2: C2.2 U1.37 | length 19
  TopLayer w0.406: U1.37@69.497,65.55 71.962,65.55 ; U1.37@70.564,65.55 71.962,65.55 ; 71.272,65.55 71.962,65.55 ; C2.2@71.903,57.576 72.331,59.38 ; C2.2@72.331,57.399 72.331,59.799 73.025,60.493 73.025,64.487 71.962,65.55 ; C2.2@72.331,57.526 72.331,59.38 ; C2.2@72.76,57.576 72.331,59.38
NetC11_1: 
NetCSEL_1: 
NetD1_K: D1.K F1.2 R30.1 R33.2 U6.7 | length 53.1
  TopLayer w0.762: D1.K@61.31,12.369 v1(60.808,10.77) ; R30.1@61.341,23.266 61.341,25.857 R30.1@61.27,23.665 ; 61.341,25.068 v1(61.163,22.25) ; v1(60.808,10.77) 60.808,9.359 F1.2@60.73,9.281 v1(60.808,10.77) ; v1(60.808,10.77) D1.K@60.808,12.446 v1(60.808,10.77) ; v1(60.808,10.77) 60.305,12.369 v1(60.808,10.77) ; v1(61.163,22.25) v1@61.341,22.25 ; v1(61.163,22.25) R33.2@61.341,20.816 ; v1(61.163,22.25) R33.2@61.26,20.734 ; v1(61.163,22.25) R30.1@61.27,23.665 ; R33.2@61.26,20.734 R33.2@61.341,20.816 ; R33.2@61.26,20.734 v1@61.341,22.25 ; R30.1@61.27,23.665 U6.7@61.341,26.568 v1@61.341,22.25 ; R30.1@61.27,23.665 v1@61.341,22.25 ; R33.2@61.341,20.816 v1@61.341,22.25
  BottomLayer w0.762: 60.706,13.575 v1(60.808,10.77) 60.706,10.871 60.706,21.742 61.214,22.25 v1(61.163,22.25) 60.706,19.02
NetD2_K: D2.K F2.2 R28.2 R30.2 U6.6 | length 59.4
  TopLayer w0.406: R30.2@58.56,23.745 58.928,24.536 ; R30.2@59.395,23.798 58.928,24.536 ; U6.6@60.071,25.857 58.928,24.536 ; U6.6@60.071,27.28 60.071,28.626 ; R28.2@64.928,29.253 60.698,29.253 60.071,28.626 ; R28.2@65.106,28.824 63.302,29.253 ; R28.2@65.106,29.682 63.302,29.253 ; R28.2@65.156,29.253 63.302,29.253 ; 58.928,24.536 60.071,25.679 U6.6@60.071,26.568 60.071,28.626 ; 58.928,24.536 58.928,23.721 R30.2@58.984,23.665 58.928,24.536
  TopLayer w0.762: F2.2@55.93,9.231 v1(55.93,10.922) ; F2.2@55.955,9.206 v1(55.93,10.922) ; D2.K@56.432,12.462 v1(55.93,10.922) ; v1(55.93,10.922) D2.K@55.93,12.541 v1(55.93,10.922) ; v1(55.93,10.922) 55.428,12.462 v1(55.93,10.922) ; v1(56.337,23.571) v1@56.487,23.721 ; v1(56.337,23.571) 58.928,23.721 v1@56.487,23.721 ; v1(56.337,23.571) 58.857,23.665 v1@56.487,23.721
  BottomLayer w0.762: v1(55.93,10.922) 55.93,23.164 v1(56.337,23.571) 55.93,20.474
NetD40_K: 
NetD41_K: 
NetD42_K: 
NetD43_K: 
NetD44_K: 
NetD45_K: 
NetD46_K: 
NetD47_K: 
NetLS1_2: LS1.2 R37.2 | length 11.3
  TopLayer w0.762: R37.2@19.677,28.485 19.677,34.206 20.887,35.416 ; 20.887,35.416 LS1.2@22.816,35.416 20.887,35.416
NetP7_1: 
NetP7_2: 
NetP7_3: 
NetR23_1: R23.1 U6.1 | length 10.7
  TopLayer w0.406: R23.1@62.249,35.597 62.611,33.775 ; U6.1@62.611,32.156 62.611,35.69 R23.1@62.679,35.758 ; U6.1@62.611,32.868 62.611,34.392 ; R23.1@62.679,35.631 62.611,33.775 ; R23.1@63.106,35.565 62.611,33.775
NetR24_2: 
NetR31_1: R31.1 R34.2 U6.2 U6.3 | length 26
  TopLayer w0.406: R31.1@59.561,35.409 60.071,33.621 ; R31.1@59.987,35.479 60.071,33.621 ; U6.3@60.071,32.156 60.071,35.522 R31.1@59.987,35.606 61.067,35.606 ; U6.3@60.071,32.868 60.071,34.392 ; R31.1@60.073,35.183 61.067,35.606 ; R31.1@60.073,36.029 61.067,35.606 ; R31.1@60.418,35.448 60.071,33.621 ; U6.2@61.341,32.156 61.366,32.182 61.366,35.306 61.067,35.606 ; U6.2@61.341,32.868 61.366,34.392
  TopLayer w0.762: R34.2@56.634,29.103 58.974,29.103 60.071,30.201 ; U6.3@60.071,31.445 60.071,30.201 ; U6.3@60.071,32.156 60.071,30.201
NetR32_1: 
NetR36_1: R36.1 U6.4 | length 11.1
  TopLayer w0.406: R36.1@56.917,35.53 57.345,33.726 ; R36.1@57.345,35.58 57.345,33.726 ; R36.1@57.345,35.707 57.345,32.723 57.912,32.156 ; R36.1@57.774,35.53 57.345,33.726 ; 57.912,32.156 U6.4@58.801,32.156 57.912,32.156
NetR41_2: 
NetR44_1: 
NetR45_2: 
NetR46_2: 
NetR47_2: 
NetR48_2: 
NetR50_2: 
NetR51_1: 
OSC1: C3.1 R3.2 U1.7 Y1.2 | length 41.2
  TopLayer w0.406: U1.7@62.487,73.373 62.487,77.574 63.144,78.232 66.091,78.232 66.904,79.045 ; U1.7@62.487,74.44 62.487,75.862 ; R3.2@64.236,86.374 65.416,86.374 ; R3.2@64.315,85.95 65.416,86.374 ; R3.2@64.315,86.799 65.416,86.374 ; Y1.2@66.354,80.364 66.979,82.248 ; Y1.2@66.36,80.136 66.904,79.045 ; C3.1@66.55,83.911 66.979,82.107 ; C3.1@66.869,84.506 65.938,84.038 ; C3.1@66.91,83.662 65.938,84.038 ; C3.1@66.979,83.961 66.979,82.107 ; C3.1@67.408,83.911 66.979,82.107 ; Y1.2@67.448,80.136 66.904,79.045 ; Y1.2@67.459,80.322 66.979,82.248 ; 65.416,86.374 65.618,86.172 65.618,84.358 65.938,84.038 ; 65.938,84.038 66.929,84.038 C3.1@66.979,84.088 ; 65.938,84.038 C3.1@66.979,84.088 ; 66.904,79.045 Y1.2@66.904,80.264 ; 66.904,79.045 Y1.2@66.904,80.264 ; Y1.2@66.904,80.264 66.979,80.339 C3.1@66.979,84.088 ; Y1.2@66.904,80.264 66.979,82.248
OSC2: C1.1 R3.1 U1.8 Y1.1 | length 53.5
  TopLayer w0.406: C1.1@61.114,83.91 61.543,82.119 ; Y1.1@61.266,80.228 61.674,78.269 ; Y1.1@61.274,80.363 61.824,81.839 ; C1.1@61.543,83.961 61.543,82.119 ; C1.1@61.593,83.659 63.397,84.088 ; C1.1@61.593,84.517 63.397,84.088 ; U1.8@61.674,73.373 61.674,80.114 Y1.1@61.824,80.264 ; U1.8@61.674,74.44 61.674,75.862 ; C1.1@61.972,83.91 61.543,82.119 ; Y1.1@62.37,80.145 61.674,78.269 ; Y1.1@62.374,80.363 61.824,81.839 ; R3.1@64.159,83.79 62.342,84.339 ; R3.1@64.159,84.386 62.342,83.837 ; R3.1@64.185,83.659 62.381,84.088 R3.1@64.185,84.517 ; R3.1@64.215,83.53 62.342,83.837 ; R3.1@64.215,84.646 62.342,84.339 ; R3.1@64.236,83.961 62.342,83.837 ; R3.1@64.236,84.215 62.342,84.339 ; 61.543,82.119 C1.1@61.543,84.088 R3.1@64.236,84.088 ; 61.543,82.119 61.824,81.839 ; 61.674,78.269 Y1.1@61.824,80.264 ; Y1.1@61.824,80.264 61.824,81.839 ; 63.397,84.088 64.124,83.671 63.397,84.088 ; 63.397,84.088 64.124,84.505 63.397,84.088 ; 63.397,84.088 R3.1@64.236,84.088 ; 63.397,84.088 R3.1@64.236,84.088
RESET1: C5.1 R12.1 U1.12 烧入口1.1 | length 60.7
  TopLayer w0.406: v1@56.113,87.756 56.416,86.055 ; v1@56.72,87.756 56.416,86.055 ; U1.12@57.051,71.138 57.051,72.161 56.416,72.796 v1(56.416,87.782) 56.416,86.055 ; 烧入口1.1@57.421,91.516 57.963,93.409 烧入口1.1@58.504,91.516 ; R12.1@57.508,95.284 57.963,93.486 ; R12.1@57.936,95.34 57.963,93.486 ; 烧入口1.1@57.963,91.44 57.963,95.441 R12.1@57.936,95.467 C5.1@60.68,95.467 58.825,95.467 ; R12.1@57.987,95.038 59.791,95.467 R12.1@57.987,95.896 ; R12.1@58.366,95.296 57.963,93.486 ; C5.1@60.629,95.038 58.825,95.467 ; C5.1@60.629,95.896 58.825,95.467
  BottomLayer w0.406: v1@56.113,87.809 56.416,89.51 v1@56.72,87.809 ; v1(56.416,87.782) 56.416,90.452 ; 烧入口1.1@57.404,91.44 56.416,90.452 ; 烧入口1.1@57.603,91.852 56.416,90.452 ; 烧入口1.1@57.963,91.44 56.416,90.452 ; 烧入口1.1@58.185,90.94 56.416,90.452
RX: P2.3 P3.2 U1.36 | length 56.6
  TopLayer w0.406: P3.2@66.42,36.197 65.38,36.728 ; P3.2@66.42,37.26 65.38,36.728 ; U1.36@69.497,64.762 71.636,64.762 ; U1.36@70.564,64.762 71.636,64.762 ; 65.38,36.728 64.973,37.135 64.973,42.933 70.333,48.293 70.333,59.825 72.238,61.73 72.238,64.16 71.636,64.762 ; 65.38,36.728 P3.2@66.548,36.728 65.38,36.728
  BottomLayer w0.406: P3.2@66.218,37.164 68.178,38.308 ; P3.2@66.973,36.384 68.178,38.308 ; P2.3@68.709,39.606 67.527,37.656 ; P2.3@69.476,38.838 67.527,37.656 ; 67.527,37.656 P2.3@69.139,39.268 66.599,36.728 P3.2@66.548,36.728 68.178,38.308
RX2: R23.2 U1.34 | length 34.9
  TopLayer w0.406: R23.2@62.251,38.221 62.679,40.025 ; R23.2@62.679,38.044 62.679,42.867 68.656,48.843 68.656,60.376 69.497,61.217 U1.34@69.497,63.162 69.497,61.74 ; R23.2@62.679,38.171 62.679,40.025 ; R23.2@63.108,38.221 62.679,40.025
SW0: 
SW1: 
SW2: 
SW3: 
SW4: 
SW5: 
SW6: 
SW7: 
